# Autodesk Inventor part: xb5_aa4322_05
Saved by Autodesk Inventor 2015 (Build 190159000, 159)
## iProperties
Created: 2018-05
Part Number: xb5_aa4322_05
Checked By: TraceParts S.A.
Material: Generic
Catalog Web Link: www.traceparts.com
Document SubType Name: Modeling
Designer: TraceParts
Density: 1 g/cm^3
Appearance: Default
Company: TraceParts S.A.
Author: TraceParts
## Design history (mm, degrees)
feature "xb5_aa4322_05.ipt"
body "Solid1"
